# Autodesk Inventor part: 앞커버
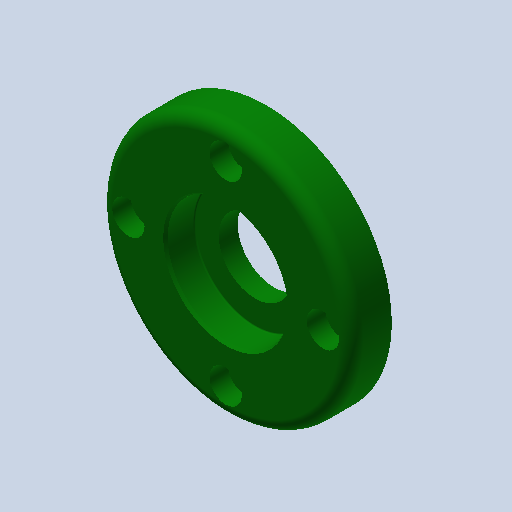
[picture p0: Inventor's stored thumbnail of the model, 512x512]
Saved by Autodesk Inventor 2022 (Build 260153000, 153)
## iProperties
Created: 2015-09
Part Number: 앞커버
Material: 알루미늄 6061
Document SubType Name: Modeling
Designer: mduedu
Density: 1 g/cm^3
Appearance: 진녹색
Author: mduedu
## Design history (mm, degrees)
sketch "스케치1"
  geometry: L1 (0, 7.5)-(0, -7.5); L2 (0, 7.5)-(31, 7.5); L3 (31, 7.5)-(31, -2.5); L4 (31, -2.5)-(17.5, -2.5); L5 (17.5, -2.5)-(17.5, -7.5); L6 (17.5, -7.5)-(0, -7.5); 2 further points
  constraints: 12 end point, 2 parallel, 2 perpendicular, 1 coincident, 1 horizontal, 1 midpoint, 1 vertical
  dimensions: "d0" = 15 distance of L1.start L1.end; "d1" = 62 diameter of L3 L1; "d2" = 35 diameter of L5 L1; "d3" = 10 distance of L2.end L3.end
revolve "회전1" sketch "스케치1" stored, may be unused: angle "d4" = 90 deg
hole "구멍1" diameter "d7" = 30; stored, may be unused: countersink angle "d11" = 90 deg, drill point angle "d13" = 0 deg; dims "d5" = 10, "d6" = 10, "d8" = 6, "d9" = 4, "d10" = 2, "d12" = 7.3
hole "구멍2" diameter "d16" = 18; stored, may be unused: countersink angle "d20" = 90 deg, drill point angle "d22" = 0 deg; dims "d14" = 10, "d15" = 10, "d17" = 6, "d18" = 4, "d19" = 2, "d21" = 7.3
chamfer "모따기2" distance "d26" = 0.7; stored, may be unused: second distance "d27" = 2, angle "d28" = 30 deg
fillet "모깎기1" dims "d29" = 0.3
sketch "스케치3"
  geometry: C1 r 15.404 at (0, 0) reference; A1 r 24 centre (0, 0) between (0, 24) and (0, -24); 2 further points
  constraints: 4 point on circle, 2 horizontal alignment, 2 vertical alignment, 1 centre point, 1 coincident
  dimensions: "d60" = 48 diameter of A1
hole "구멍3" sketch "스케치3" at (0, 24), (-24, 0), (24, 0), (0, -24) diameter "d36" = 4.5; stored, may be unused: countersink angle "d40" = 90 deg, drill point angle "d42" = 0 deg; dims "d37" = 6, "d38" = 8, "d39" = 4.6, "d41" = 8
chamfer "모따기3" distance "d43" = 1; stored, may be unused: second distance "d44" = 2, angle "d45" = 45 deg
fillet "모깎기2" dims "d46" = 3
hole "구멍4" diameter "d49" = 30; stored, may be unused: countersink angle "d53" = 90 deg, drill point angle "d55" = 0 deg; dims "d50" = 6, "d51" = 4, "d52" = 2, "d54" = 3, "d56" = 10, "d57" = 10
fillet "모깎기3" dims "d58" = 3
node "솔리드1"
sketch "스케치2" dims "d30" = 48
  geometry: 6 further points
  constraints: 2 vertical alignment, 1 coincident, 7 other
  dimensions: "d34" = 360 deg dimension on point (0, 0) point (0, 24) (derived)
